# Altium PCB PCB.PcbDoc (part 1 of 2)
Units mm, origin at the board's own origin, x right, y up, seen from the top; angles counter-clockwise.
Board outline 41 x 25.36 mm, 4 copper layers (TOP, GND, SIG, BOTTOM), stack 1.586 mm thick; 138 components, 30 nets, 293 pads, 110 vias.
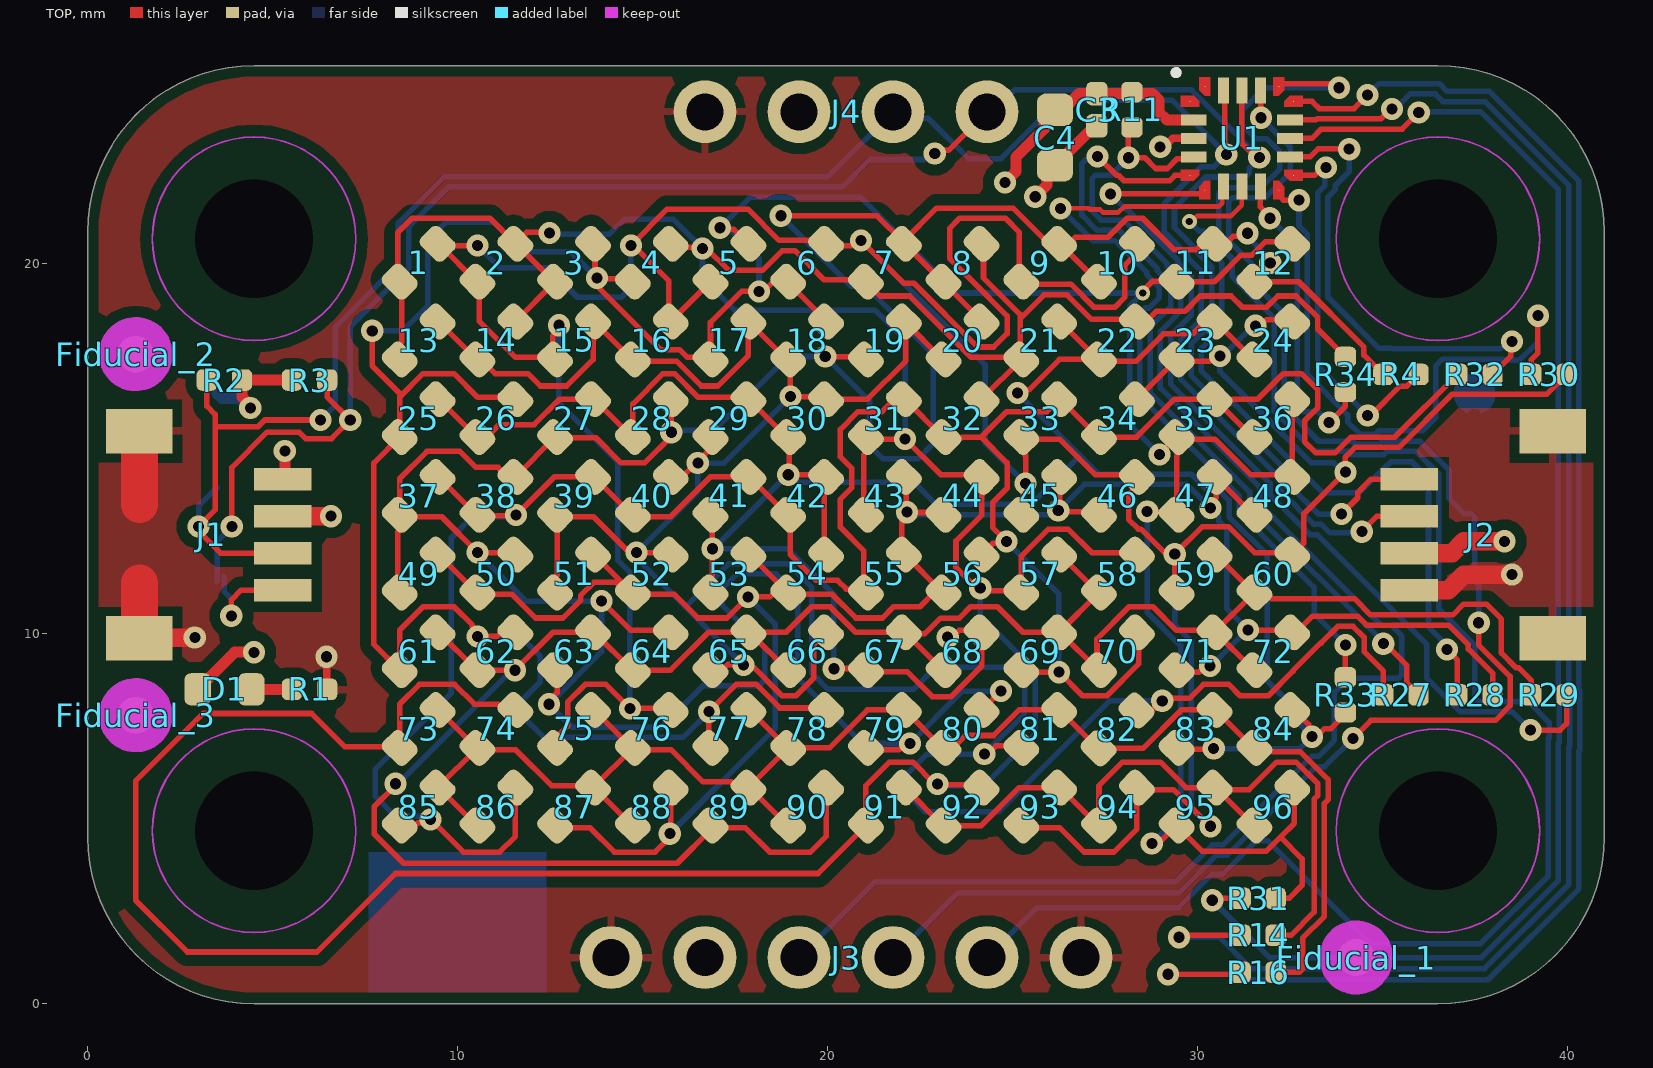
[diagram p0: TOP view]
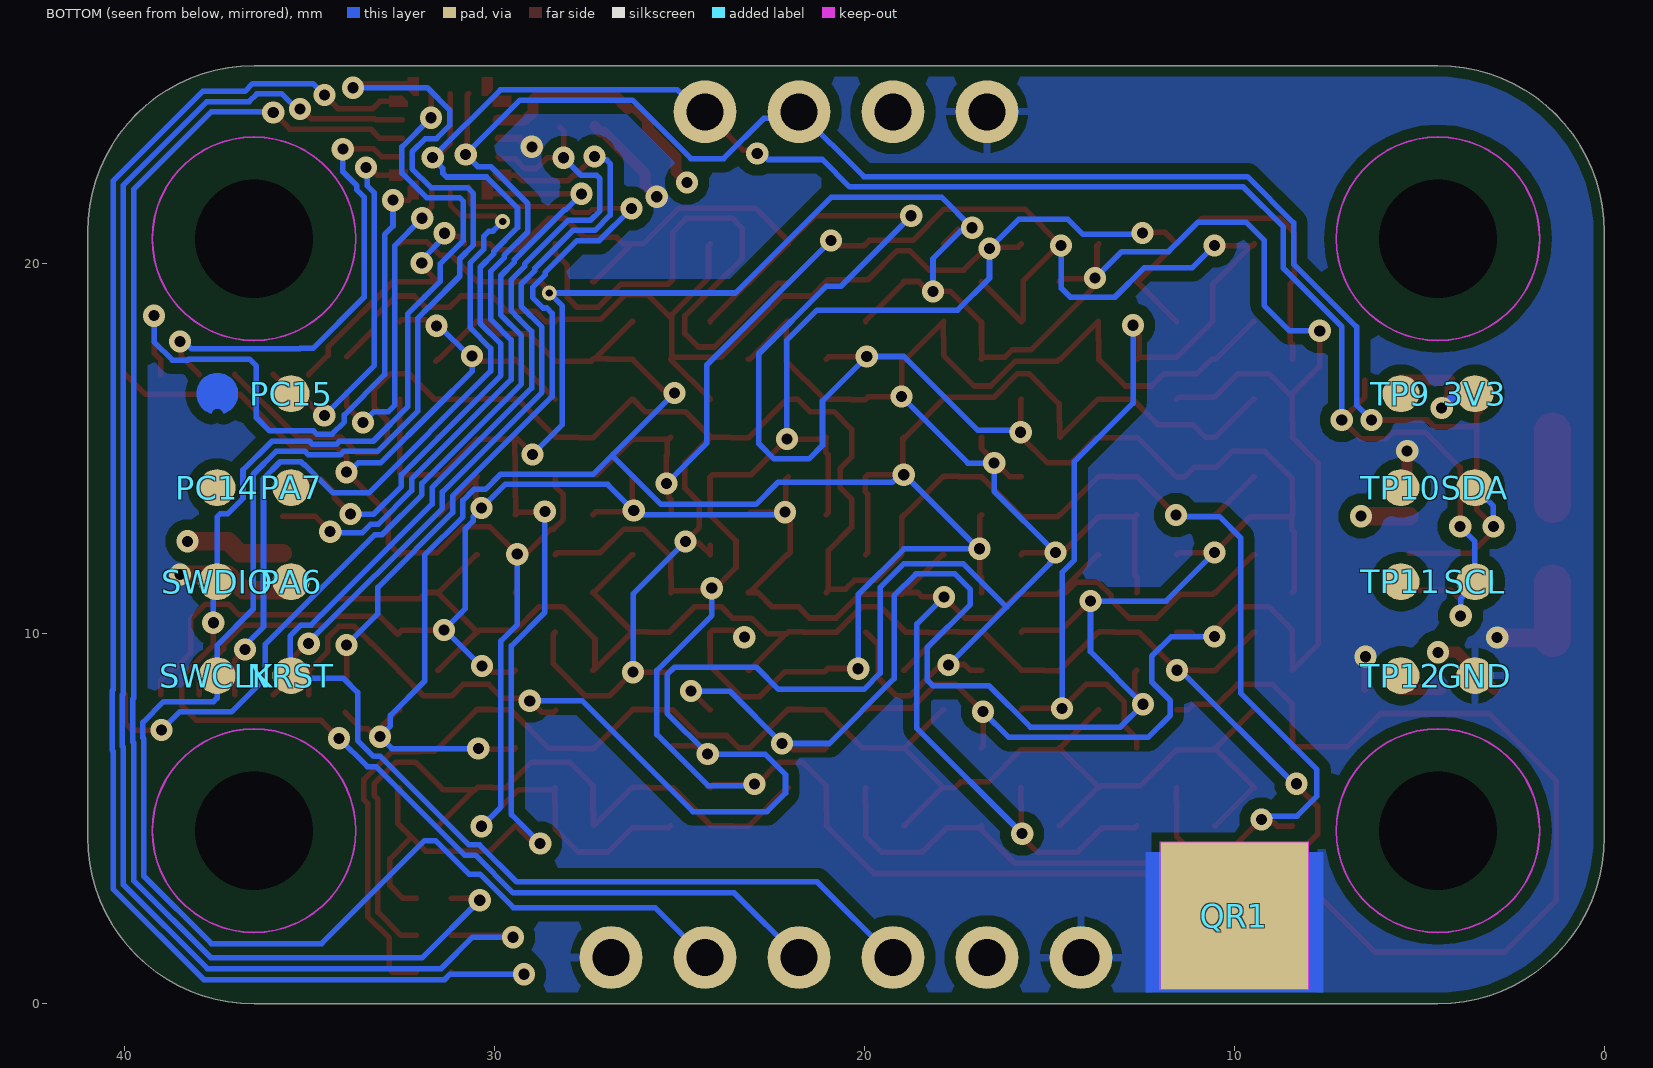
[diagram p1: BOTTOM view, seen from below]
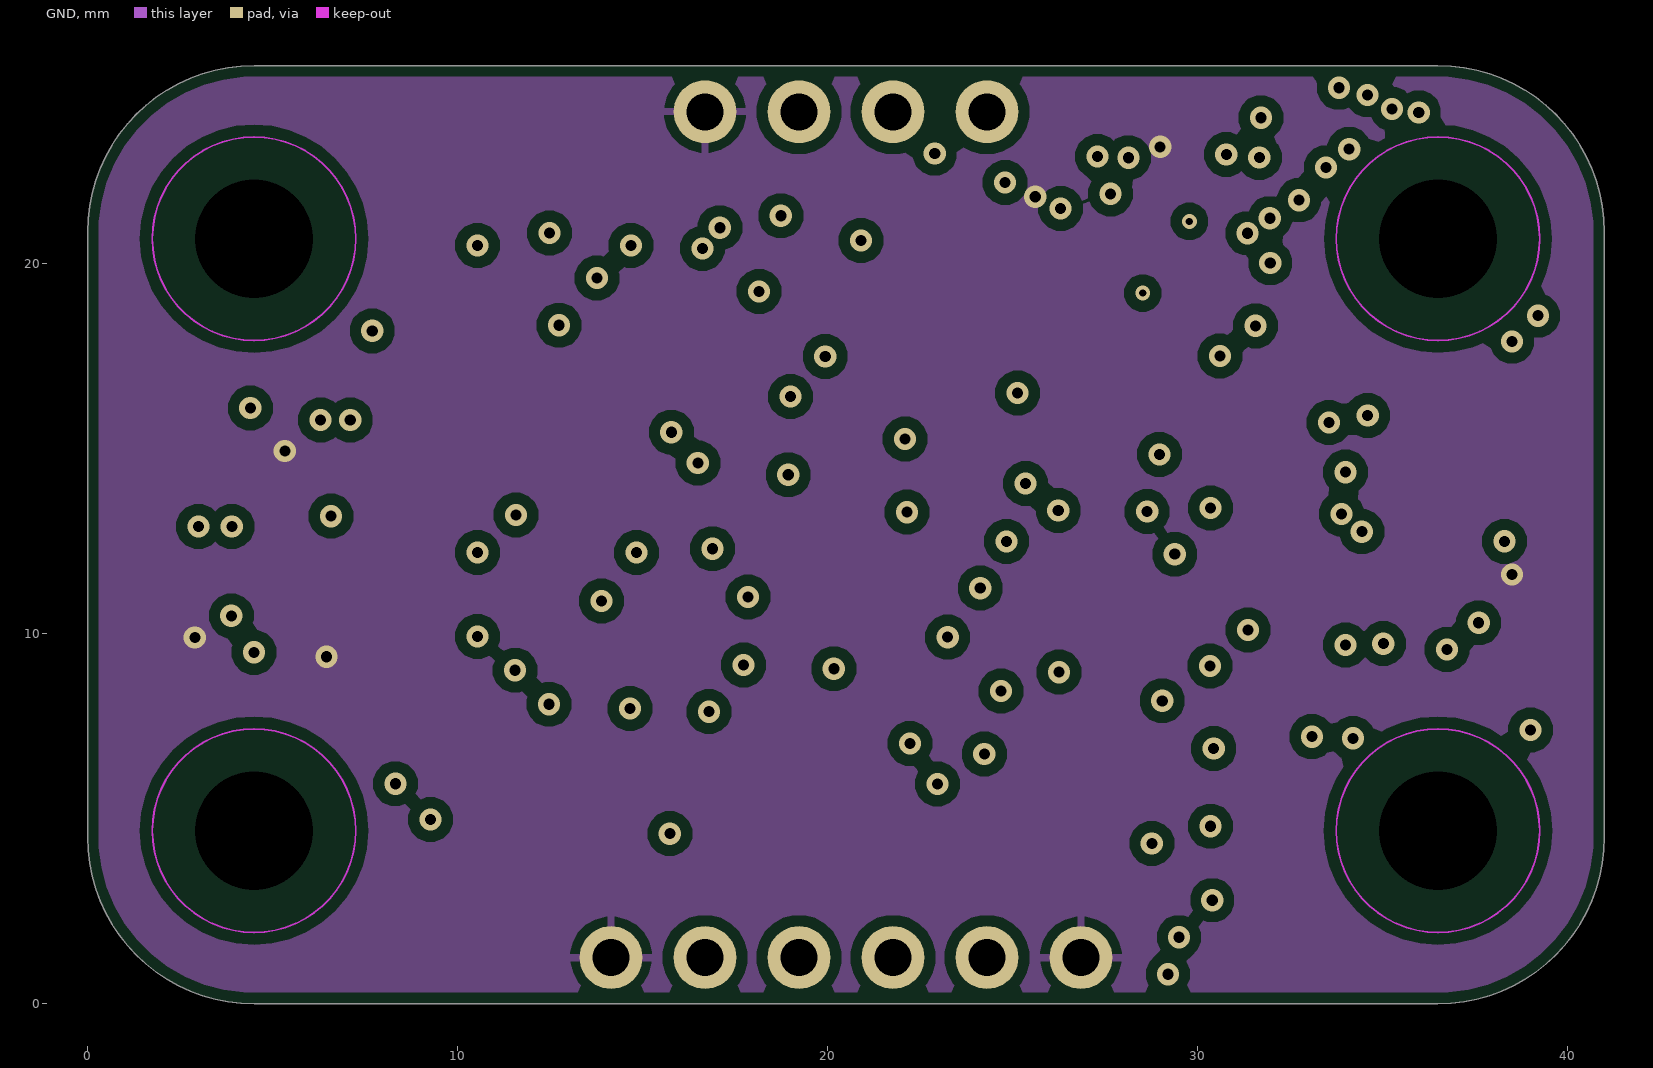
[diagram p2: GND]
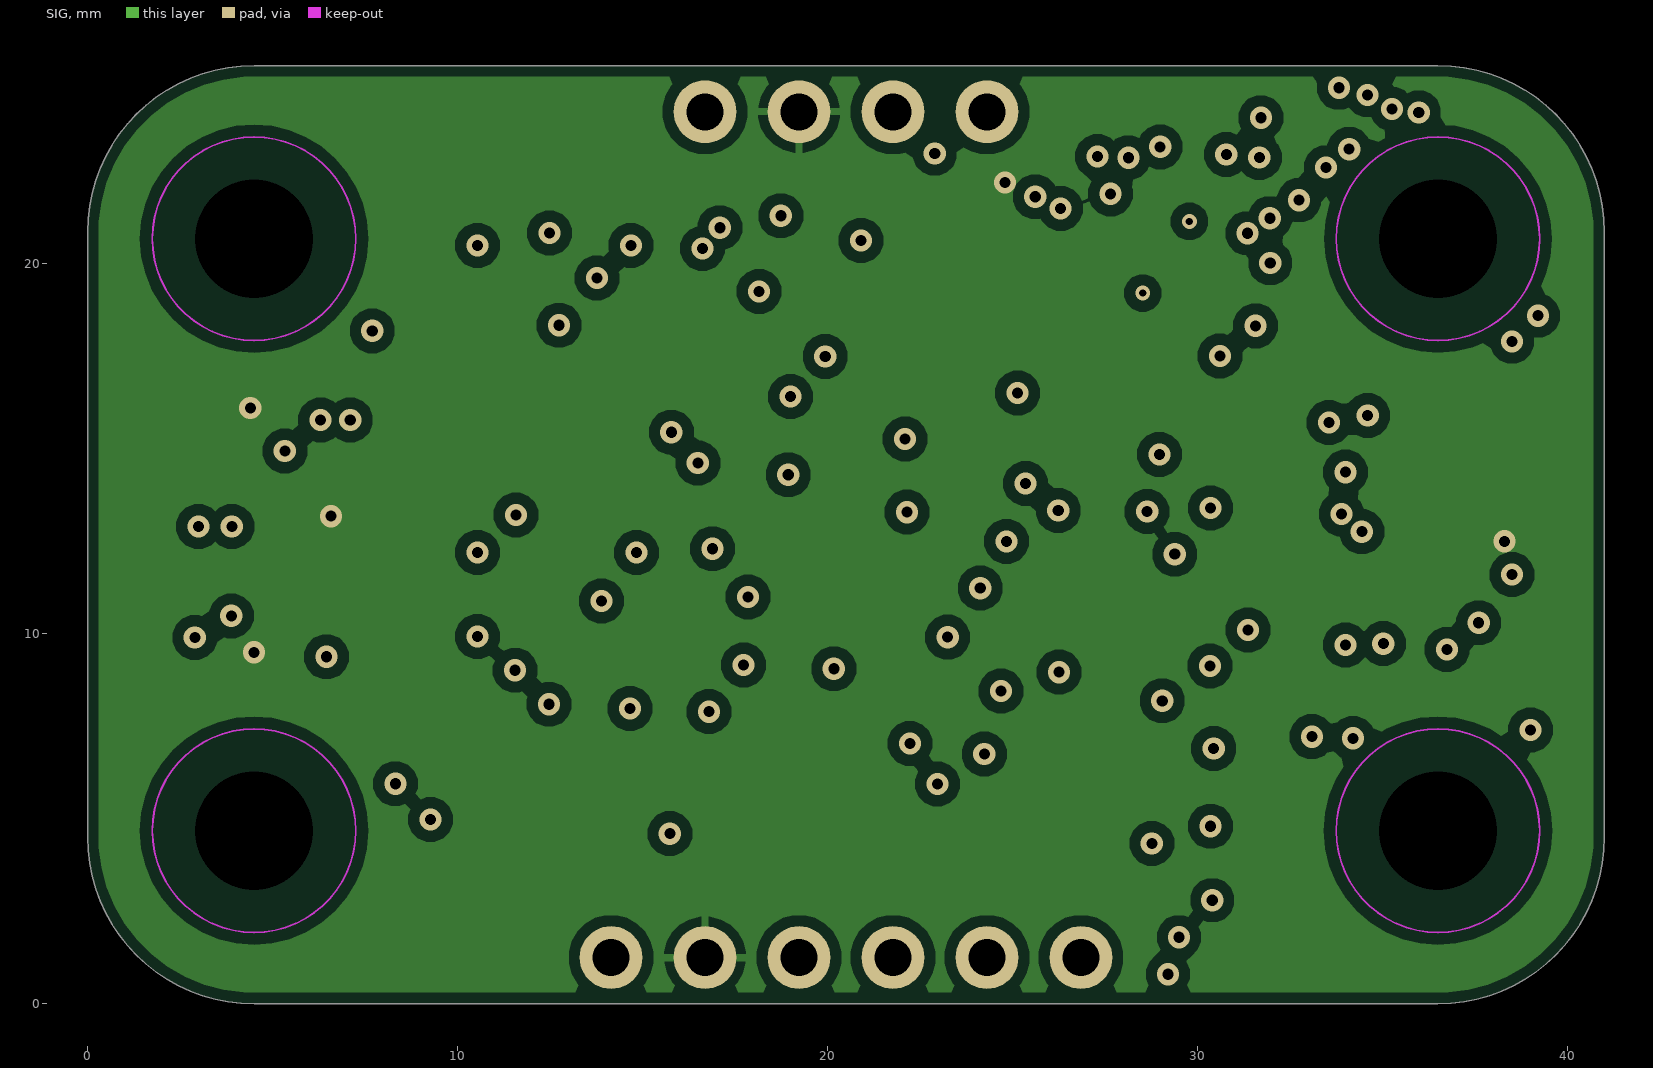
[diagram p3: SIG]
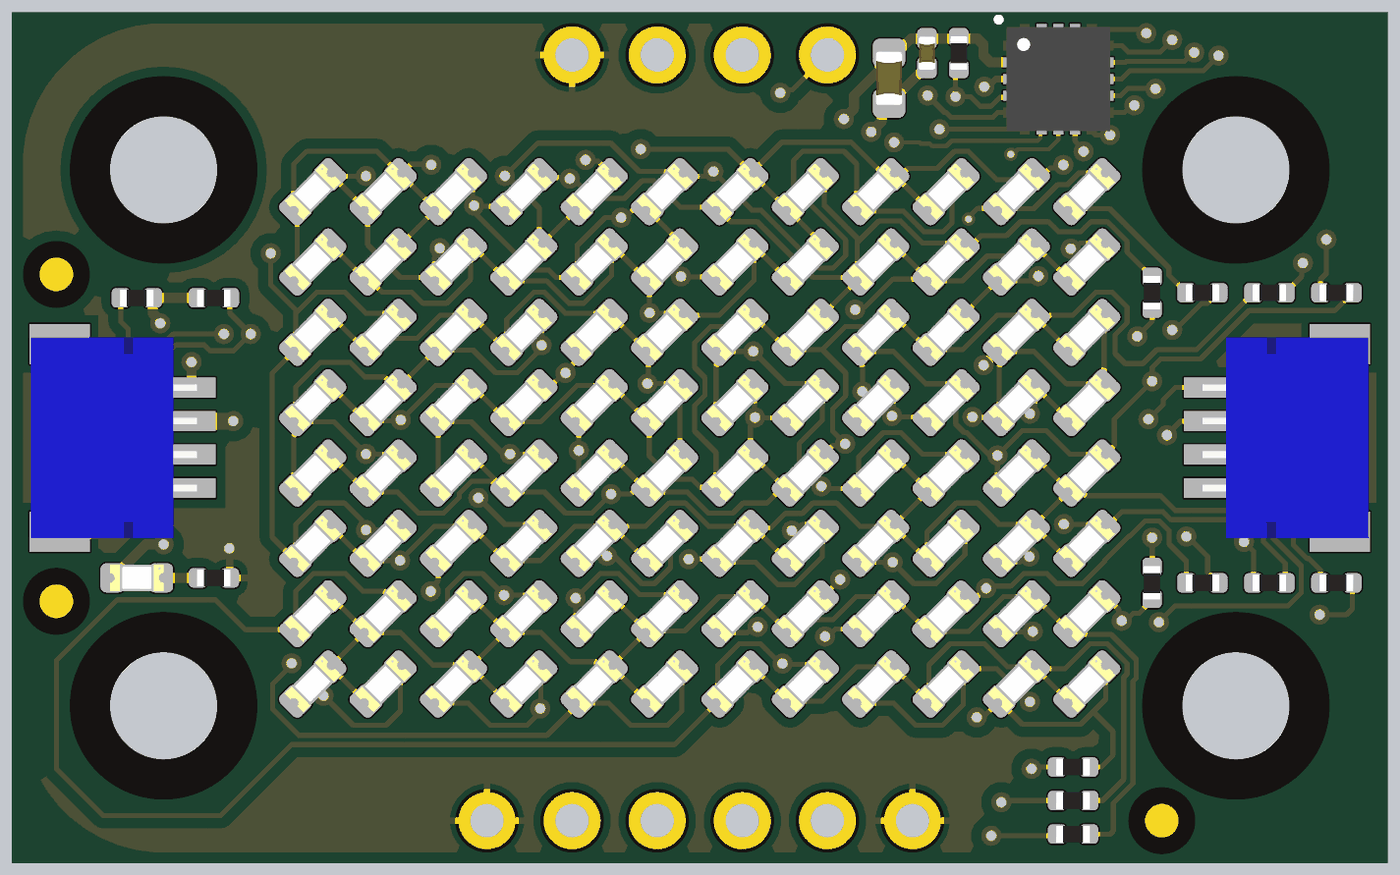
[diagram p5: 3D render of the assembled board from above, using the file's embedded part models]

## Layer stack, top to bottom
Top Solder: solder mask 0.01, Solder Resist, Dk 3.5
TOP: signal copper 0.018
Dielectric 1: prepreg 0.14, PP-014, Dk 4.2
GND: signal copper 0.035
Dielectric2: core 1.2, FR-4, Dk 4.8
SIG: signal copper 0.035
Dielectric3: prepreg 0.14, PP-014, Dk 4.2
BOTTOM: signal copper 0.018
Bottom Solder: solder mask 0.01, Solder Resist, Dk 3.5

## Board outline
0,4.5 ccw(c4.5,4.5) 4.5,0 36.5,0 ccw(c36.5,4.5) 41,4.5 41,20.86 ccw(c36.5,20.86) 36.5,25.36 4.5,25.36 ccw(c4.5,20.86) 0,20.86

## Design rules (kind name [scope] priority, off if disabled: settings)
BoardOutlineClearance Mousebites [(ObjectKind = 'Pad') And (Name = 'Free-MOUSEBITE')] p1: gap=0 ignorepadtopadclearanceinfootprint=FALSE
BoardOutlineClearance Silks [(OnLayer('Top Overlay') OR OnLayer('Bottom Overlay'))] p2: gap=0 ignorepadtopadclearanceinfootprint=FALSE
BoardOutlineClearance [All] p3: gap=0.3 ignorepadtopadclearanceinfootprint=FALSE
Clearance COPPER_0.3mm [All] p1: gap=0.127 ignorepadtopadclearanceinfootprint=FALSE except(0.3: Arc-Fill Arc-Poly Arc-Region Track-Fill Track-Poly Track-Region SMDPad-Fill SMDPad-Poly SMDPad-Region THPad-Fill THPad-Poly THPad-Region Via-Fill Via-Poly Via-Region Fill-Fill Fill-Poly Fill-Region Poly-Poly Poly-Region Region-Region)
Clearance "Generic clearance 0.15mm" [All] p2: gap=0.127 ignorepadtopadclearanceinfootprint=FALSE
ComponentClearance [All] p1: gap=0.2 collisioncheckmode=3 verticalgap=0 showdistances=TRUE
DiffPairsRouting USB [InDifferentialPairClass('USB')] p1: maxlimit=0.15 minlimit=0.15 mostfreqgap=0.15 toplayer_minwidth=0.15 toplayer_maxwidth=0.21 toplayer_prefwidth=0.2 midlayer1_minwidth=0.381 midlayer1_maxwidth=0.381 midlayer1_prefwidth=0.381 midlayer2_minwidth=0.381 midlayer2_maxwidth=0.381 midlayer2_prefwidth=0.381 bottomlayer_minwidth=0.15 bottomlayer_maxwidth=0.21 bottomlayer_prefwidth=0.2 impedanceprofiledriven=TRUE maxuncoupledlength=12.7
Height [All] p1: minheight=0 maxheight=30 prefheight=12.7
HoleSize [All] p1: absolutevalues=TRUE maxlimit=30 minlimit=0.2 maxpercent=80.000 minpercent=20.000
HoleToHoleClearance [All] p1: gap=0.25 allowstackedmicrovias=FALSE
MinimumAnnularRing [All] p1: minimumring=0.1
PlaneConnect [All] p1: pad.planeconnectstyle=Relief pad.reliefexpansion=0.508 pad.reliefentries=4 pad.reliefconductorwidth=0.254 pad.reliefairgap=0.254 via.planeconnectstyle=Direct via.reliefexpansion=0.508 via.reliefentries=4 via.reliefconductorwidth=0.254 via.reliefairgap=0.254
PolygonConnect [All] p1: thpad.connectstyle=Relief thpad.reliefconductorwidth=0.2 thpad.reliefentries=4 thpad.polygonreliefangle="90 Angle" thpad.airgapwidth=0.254 smdpad.connectstyle=Relief smdpad.reliefconductorwidth=0.2 smdpad.reliefentries=4 smdpad.polygonreliefangle="90 Angle" smdpad.airgapwidth=0.254 via.connectstyle=Direct via.reliefconductorwidth=0.254 via.reliefentries=4 via.polygonreliefangle="90 Angle" via.airgapwidth=0.254
RoomDefinition TOP [InComponentClass('TOP')] p1: confinementstyle=ConfineIn formatcopy=TRUE lockcomponents=FALSE outline 42.1,5.4 49.2,5.4 49.2,22.3 42.1,22.3
RoutingVias StandardVias [All] p1: holewidth=0.3 width=0.6 viastyle="Through Hole" minholewidth=0.2 minwidth=0.4 maxholewidth=0.3 maxwidth=0.6
SMDToCorner [All] p1: distance=39370
SilkToSilkClearance [All] p1: silktosilkclearance=0.2
SilkToSolderMaskClearance [IsPad] p1: minsilkscreentomaskgap=0.15 clearancetoexposedcopper=TRUE
SolderMaskExpansion VIAtented [IsVia] p1: expansion=0.102 istentingtop=TRUE
SolderMaskExpansion [All] p2: expansion=0.05 istentingtop=FALSE
SupplyNets "Schematic Supply Nets_1" [InNet('+3V3')] p1: voltage=0.000
SupplyNets "Schematic Supply Nets" [InNet('GND')] p2: voltage=0.000
UnConnectedPin [All] p1:
UnRoutedNet [NOT WithinRoom('K36')] p1: checkbadconnections=TRUE
ViasUnderSMD [All] p1: allowed=FALSE
Width StandardTraces [All] p1: maxlimit=5 minlimit=0.127 preferedwidth=0.15 bottomlayer_minwidth=0.15 minimp=50.000000 maximp=50.000000 favimp=50.000000
21 further rules are at their usual default settings.

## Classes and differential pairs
component class U_LEDMATRIX: 1 2 3 4 5 6 7 8 9 10 11 12 13 14 15 16 17 18 19 20 21 22 23 24 25 26 27 28 29 30 31 32 33 34 35 36 37 38 39 40 41 42 43 44 45 46 47 48 49 50 51 52 53 54 55 56 57 58 59 60 61 62 63 64 65 66 67 68 69 70 71 72 73 74 75 76 77 78 79 80 81 82 83 84 85 86 87 88 89 90 91 92 93 94 95 96 R4 R14 R16 R27 R28 R29 R30 R31 R32 R33 R34
component class U_MICROCONTROLLER: C3 C4 R2 R3 R11 U1
component class TOP: 3V3 D1 Fiducial_1 Fiducial_2 Fiducial_3 GND J1 J2 J3 J4 NRST PA6 PA7 PC14 PC15 QR1 R1 SCL SDA SWCLK SWDIO TP9 TP10 TP11 TP12

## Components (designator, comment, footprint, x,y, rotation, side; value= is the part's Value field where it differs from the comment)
1 "LTST-C191TBKT-5A" LEDC1608X80N-AK 8.951,20.03 r225 top
2 "LTST-C191TBKT-5A" LEDC1608X80N-AK 11.051,20.03 r225 top
3 "LTST-C191TBKT-5A" LEDC1608X80N-AK 13.151,20.03 r225 top
3V3 "Test point 1.00mm" TP-1.00MM 3.5,16.49 r90 bottom
4 "LTST-C191TBKT-5A" LEDC1608X80N-AK 15.251,20.03 r225 top
5 "LTST-C191TBKT-5A" LEDC1608X80N-AK 17.351,20.03 r225 top
6 "LTST-C191TBKT-5A" LEDC1608X80N-AK 19.451,20.03 r225 top
7 "LTST-C191TBKT-5A" LEDC1608X80N-AK 21.551,20.03 r225 top
8 "LTST-C191TBKT-5A" LEDC1608X80N-AK 23.651,20.03 r225 top
9 "LTST-C191TBKT-5A" LEDC1608X80N-AK 25.751,20.03 r225 top
10 "LTST-C191TBKT-5A" LEDC1608X80N-AK 27.851,20.03 r225 top
11 "LTST-C191TBKT-5A" LEDC1608X80N-AK 29.951,20.03 r225 top
12 "LTST-C191TBKT-5A" LEDC1608X80N-AK 32.051,20.03 r225 top
13 "LTST-C191TBKT-5A" LEDC1608X80N-AK 8.951,17.93 r225 top
14 "LTST-C191TBKT-5A" LEDC1608X80N-AK 11.051,17.93 r225 top
15 "LTST-C191TBKT-5A" LEDC1608X80N-AK 13.151,17.93 r225 top
16 "LTST-C191TBKT-5A" LEDC1608X80N-AK 15.251,17.93 r225 top
17 "LTST-C191TBKT-5A" LEDC1608X80N-AK 17.351,17.93 r225 top
18 "LTST-C191TBKT-5A" LEDC1608X80N-AK 19.451,17.93 r225 top
19 "LTST-C191TBKT-5A" LEDC1608X80N-AK 21.551,17.93 r225 top
20 "LTST-C191TBKT-5A" LEDC1608X80N-AK 23.65,17.93 r225 top
21 "LTST-C191TBKT-5A" LEDC1608X80N-AK 25.75,17.93 r225 top
22 "LTST-C191TBKT-5A" LEDC1608X80N-AK 27.85,17.93 r225 top
23 "LTST-C191TBKT-5A" LEDC1608X80N-AK 29.951,17.93 r225 top
24 "LTST-C191TBKT-5A" LEDC1608X80N-AK 32.051,17.93 r225 top
25 "LTST-C191TBKT-5A" LEDC1608X80N-AK 8.951,15.83 r225 top
26 "LTST-C191TBKT-5A" LEDC1608X80N-AK 11.051,15.83 r225 top
27 "LTST-C191TBKT-5A" LEDC1608X80N-AK 13.151,15.83 r225 top
28 "LTST-C191TBKT-5A" LEDC1608X80N-AK 15.251,15.83 r225 top
29 "LTST-C191TBKT-5A" LEDC1608X80N-AK 17.351,15.83 r225 top
30 "LTST-C191TBKT-5A" LEDC1608X80N-AK 19.451,15.83 r225 top
31 "LTST-C191TBKT-5A" LEDC1608X80N-AK 21.551,15.83 r225 top
32 "LTST-C191TBKT-5A" LEDC1608X80N-AK 23.65,15.83 r225 top
33 "LTST-C191TBKT-5A" LEDC1608X80N-AK 25.75,15.83 r225 top
34 "LTST-C191TBKT-5A" LEDC1608X80N-AK 27.851,15.83 r225 top
35 "LTST-C191TBKT-5A" LEDC1608X80N-AK 29.951,15.83 r225 top
36 "LTST-C191TBKT-5A" LEDC1608X80N-AK 32.051,15.83 r225 top
37 "LTST-C191TBKT-5A" LEDC1608X80N-AK 8.951,13.73 r225 top
38 "LTST-C191TBKT-5A" LEDC1608X80N-AK 11.051,13.73 r225 top
39 "LTST-C191TBKT-5A" LEDC1608X80N-AK 13.151,13.73 r225 top
40 "LTST-C191TBKT-5A" LEDC1608X80N-AK 15.251,13.73 r225 top
41 "LTST-C191TBKT-5A" LEDC1608X80N-AK 17.351,13.73 r225 top
42 "LTST-C191TBKT-5A" LEDC1608X80N-AK 19.451,13.73 r225 top
43 "LTST-C191TBKT-5A" LEDC1608X80N-AK 21.551,13.73 r225 top
44 "LTST-C191TBKT-5A" LEDC1608X80N-AK 23.65,13.73 r225 top
45 "LTST-C191TBKT-5A" LEDC1608X80N-AK 25.751,13.73 r225 top
46 "LTST-C191TBKT-5A" LEDC1608X80N-AK 27.851,13.73 r225 top
47 "LTST-C191TBKT-5A" LEDC1608X80N-AK 29.951,13.73 r225 top
48 "LTST-C191TBKT-5A" LEDC1608X80N-AK 32.051,13.73 r225 top
49 "LTST-C191TBKT-5A" LEDC1608X80N-AK 8.951,11.63 r225 top
50 "LTST-C191TBKT-5A" LEDC1608X80N-AK 11.051,11.63 r225 top
51 "LTST-C191TBKT-5A" LEDC1608X80N-AK 13.151,11.63 r225 top
52 "LTST-C191TBKT-5A" LEDC1608X80N-AK 15.251,11.63 r225 top
53 "LTST-C191TBKT-5A" LEDC1608X80N-AK 17.351,11.63 r225 top
54 "LTST-C191TBKT-5A" LEDC1608X80N-AK 19.45,11.63 r225 top
55 "LTST-C191TBKT-5A" LEDC1608X80N-AK 21.55,11.63 r225 top
56 "LTST-C191TBKT-5A" LEDC1608X80N-AK 23.651,11.63 r225 top
57 "LTST-C191TBKT-5A" LEDC1608X80N-AK 25.751,11.63 r225 top
58 "LTST-C191TBKT-5A" LEDC1608X80N-AK 27.851,11.63 r225 top
59 "LTST-C191TBKT-5A" LEDC1608X80N-AK 29.951,11.63 r225 top
60 "LTST-C191TBKT-5A" LEDC1608X80N-AK 32.051,11.63 r225 top
61 "LTST-C191TBKT-5A" LEDC1608X80N-AK 8.95,9.529 r225 top
62 "LTST-C191TBKT-5A" LEDC1608X80N-AK 11.051,9.53 r225 top
63 "LTST-C191TBKT-5A" LEDC1608X80N-AK 13.151,9.53 r225 top
64 "LTST-C191TBKT-5A" LEDC1608X80N-AK 15.251,9.53 r225 top
65 "LTST-C191TBKT-5A" LEDC1608X80N-AK 17.351,9.53 r225 top
66 "LTST-C191TBKT-5A" LEDC1608X80N-AK 19.451,9.53 r225 top
67 "LTST-C191TBKT-5A" LEDC1608X80N-AK 21.551,9.53 r225 top
68 "LTST-C191TBKT-5A" LEDC1608X80N-AK 23.651,9.53 r225 top
69 "LTST-C191TBKT-5A" LEDC1608X80N-AK 25.751,9.53 r225 top
70 "LTST-C191TBKT-5A" LEDC1608X80N-AK 27.851,9.53 r225 top
71 "LTST-C191TBKT-5A" LEDC1608X80N-AK 29.951,9.53 r225 top
72 "LTST-C191TBKT-5A" LEDC1608X80N-AK 32.051,9.53 r225 top
73 "LTST-C191TBKT-5A" LEDC1608X80N-AK 8.951,7.43 r225 top
74 "LTST-C191TBKT-5A" LEDC1608X80N-AK 11.051,7.43 r225 top
75 "LTST-C191TBKT-5A" LEDC1608X80N-AK 13.151,7.43 r225 top
76 "LTST-C191TBKT-5A" LEDC1608X80N-AK 15.251,7.43 r225 top
77 "LTST-C191TBKT-5A" LEDC1608X80N-AK 17.351,7.43 r225 top
78 "LTST-C191TBKT-5A" LEDC1608X80N-AK 19.451,7.43 r225 top
79 "LTST-C191TBKT-5A" LEDC1608X80N-AK 21.551,7.43 r225 top
80 "LTST-C191TBKT-5A" LEDC1608X80N-AK 23.651,7.43 r225 top
81 "LTST-C191TBKT-5A" LEDC1608X80N-AK 25.751,7.43 r225 top
82 "LTST-C191TBKT-5A" LEDC1608X80N-AK 27.838,7.417 r225 top
83 "LTST-C191TBKT-5A" LEDC1608X80N-AK 29.951,7.43 r225 top
84 "LTST-C191TBKT-5A" LEDC1608X80N-AK 32.051,7.43 r225 top
85 "LTST-C191TBKT-5A" LEDC1608X80N-AK 8.951,5.33 r225 top
86 "LTST-C191TBKT-5A" LEDC1608X80N-AK 11.051,5.33 r225 top
87 "LTST-C191TBKT-5A" LEDC1608X80N-AK 13.151,5.33 r225 top
88 "LTST-C191TBKT-5A" LEDC1608X80N-AK 15.251,5.33 r225 top
89 "LTST-C191TBKT-5A" LEDC1608X80N-AK 17.351,5.33 r225 top
90 "LTST-C191TBKT-5A" LEDC1608X80N-AK 19.451,5.33 r225 top
91 "LTST-C191TBKT-5A" LEDC1608X80N-AK 21.551,5.33 r225 top
92 "LTST-C191TBKT-5A" LEDC1608X80N-AK 23.651,5.33 r225 top
93 "LTST-C191TBKT-5A" LEDC1608X80N-AK 25.751,5.33 r225 top
94 "LTST-C191TBKT-5A" LEDC1608X80N-AK 27.851,5.33 r225 top
95 "LTST-C191TBKT-5A" LEDC1608X80N-AK 29.951,5.33 r225 top
96 "LTST-C191TBKT-5A" LEDC1608X80N-AK 32.051,5.33 r225 top
C3 "0402B104K160CT" CAP-0402 27.28,24.165 r270 top value=100nF
C4 "GRM188R61C475KAAJD" CAP-0603 26.15,23.415 r90 top value=4.7µF
D1 "HSMG-C190" LEDC1608X80N-AK 3.7,8.5 r180 top
Fiducial_1 "Fiducial mark 1mm" "Fiducial mark 1mm-Footprint-1" 34.29,1.25 r270 top
Fiducial_2 "Fiducial mark 1mm" "Fiducial mark 1mm-Footprint-1" 1.3,17.56 r270 top
Fiducial_3 "Fiducial mark 1mm" "Fiducial mark 1mm-Footprint-1" 1.3,7.8 r270 top
GND "Test point 1.00mm" TP-1.00MM 3.5,8.87 r90 bottom
J1 "SM04B-SRSS-TB(LF)(SN)" SM04B-SRSS-TB(LF)(SN)-Footprint-1 3.337,12.68 r90 top locked
J2 "SM04B-SRSS-TB(LF)(SN)" SM04B-SRSS-TB(LF)(SN)-Footprint-1 37.663,12.68 r270 top locked
J3 "HEADER TH 2.54mm VERT. 1x006POS" "PIN HEADER 2.54mm VERT. 1x6POS" 20.5,1.25 r0 top
J4 "HEADER TH 2.54mm VERT. 1x004POS" "PIN HEADER 2.54mm VERT. 1x4POS-Footprint-1" 20.5,24.11 r0 top
NRST "Test point 1.00mm" TP-1.00MM 35.5,8.87 r180 bottom
PA6 "Test point 1.00mm" TP-1.00MM 35.5,11.41 r180 bottom
PA7 "Test point 1.00mm" TP-1.00MM 35.5,13.95 r180 bottom
PC14 "Test point 1.00mm" TP-1.00MM 37.5,13.95 r180 bottom
PC15 "Test point 1.00mm" TP-1.00MM 35.5,16.49 r180 bottom
QR1 "QR CODE 4x4mm" "QR CODE 4x4mm" 10,2.38 r180 bottom
R1 "CRCW04021K00FKEDC" RES-0402 6,8.5 r180 top value=1k
R2 "RC0402FR-074K7L" RES-0402 3.7,16.86 r0 top value=4.7k
R3 "RC0402FR-074K7L" RES-0402 6,16.86 r180 top value=4.7k
R4 "RC0402FR-0710RL" RES-0402 35.5,17.01 r0 top value=10
R11 "RC0402FR-074K7L" RES-0402 28.23,24.165 r270 top value=4.7k
R14 "RC0402FR-0710RL" RES-0402 31.64,1.85 r180 top value=10
R16 "RC0402FR-0710RL" RES-0402 31.64,0.85 r180 top value=10
R27 "RC0402FR-0710RL" RES-0402 35.5,8.35 r0 top value=10
R28 "RC0402FR-0710RL" RES-0402 37.5,8.35 r180 top value=10
R29 "RC0402FR-0710RL" RES-0402 39.5,8.35 r0 top value=10
R30 "RC0402FR-0710RL" RES-0402 39.5,17.01 r180 top value=10
R31 "RC0402FR-0710RL" RES-0402 31.64,2.85 r180 top value=10
R32 "RC0402FR-0710RL" RES-0402 37.5,17.01 r0 top value=10
R33 "RC0402FR-0710RL" RES-0402 34,8.35 r90 top value=10
R34 "RC0402FR-0710RL" RES-0402 34,17.01 r270 top value=10
SCL "Test point 1.00mm" TP-1.00MM 3.5,11.41 r90 bottom
SDA "Test point 1.00mm" TP-1.00MM 3.5,13.95 r90 bottom
SWCLK "Test point 1.00mm" TP-1.00MM 37.5,8.87 r180 bottom
SWDIO "Test point 1.00mm" TP-1.00MM 37.5,11.41 r180 bottom
TP9 "Test point 1.00mm" TP-1.00MM 5.5,16.49 r0 bottom
TP10 "Test point 1.00mm" TP-1.00MM 5.5,13.95 r0 bottom
TP11 "Test point 1.00mm" TP-1.00MM 5.5,11.41 r0 bottom
TP12 "Test point 1.00mm" TP-1.00MM 5.5,8.87 r0 bottom
U1 "STM32C011F6U6TR" UFQFPN20 31.2,23.39 r0 top

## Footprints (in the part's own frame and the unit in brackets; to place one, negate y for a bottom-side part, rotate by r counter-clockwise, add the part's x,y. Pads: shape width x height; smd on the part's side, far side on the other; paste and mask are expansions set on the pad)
CAP-0402 [mm] "Chip Capacitor, 2-Leads, Body  0402 (in) 1005 (mm), IPC Medium Density"
  rrect52% 0.63x0.58 smd mask+0.05: 1(-0.435,0) 2(0.435,0)
  body extent -0.5,-0.25 0.5,0.25, height 0.5
CAP-0603 [mm] "Chip Capacitor, Body 0603 imperial,1.6x0.8mm, IPC High Density"
  rrect51% 0.87x0.97 smd mask+0.05: 1(-0.75,0) 2(0.75,0)
  body extent -0.8,-0.4 0.8,0.4, height 0.8
"Fiducial mark 1mm-Footprint-1" [mm]
  round 1 smd paste-10 mask+0.5: 1(0,0)
  TOP keep-out circle w1: c0,0 r0.5
LEDC1608X80N-AK [mm]
  rrect50% 0.72x0.87 smd: A(0.725,0) C(-0.725,0)
  body extent -0.8,-0.4 0.8,0.4, height 0.79
"PIN HEADER 2.54mm VERT. 1x4POS-Footprint-1" [mm]
  round 1.7 hole 1 mask+0.1: 1(-3.81,0) 2(-1.27,0) 3(1.27,0) 4(3.81,0)
"PIN HEADER 2.54mm VERT. 1x6POS" [mm]
  round 1.7 hole 1 mask+0.1: 1(-6.35,0) 2(-3.81,0) 3(-1.27,0) 4(1.27,0) 5(3.81,0) 6(6.35,0)
"QR CODE 4x4mm" [mm]
  rect 4x4 smd paste-2539.97 mask+0.1: PAD(0,0)
  TOP keep-out region: -2,2 2,2 2,-2 -2,-2
RES-0402 [mm] "Chip Resistor, 2-Leads, Body  0402 (in) 1005 (mm), IPC Medium Density"
  rrect51% 0.55x0.58 smd mask+0.05: 1(-0.475,0) 2(0.475,0)
  body extent -0.5,-0.25 0.5,0.25, height 0.34
SM04B-SRSS-TB(LF)(SN)-Footprint-1 [mm]
  rect 0.6x1.55 smd mask+0.05: 1(1.5,-1.937) 2(0.5,-1.937) 3(-0.5,-1.937) 4(-1.5,-1.937)
  rect 1.2x1.8 smd mask+0.05: FIX(-2.8,1.938) FIX(2.8,1.938)
  body extent -3,-2.16 3,2.8, height 2.98
TP-1.00MM [mm]
  rrect100% 1x1 smd paste-2.54: X(0,0)
UFQFPN20 [mm] "QFN, 20-Leads, Body 3.00x3.00mm, Pitch 0.50mm, IPC Medium Density"
  round 0.025 smd mask+0.05: 1(-1.4,1) 5(-1.4,-1) 6(-1,-1.4) 10(1,-1.4) 11(1.4,-1) 15(1.4,1) 16(1,1.4) 20(-1,1.4)
  rect 0.7x0.3 smd mask+0.05: 2(-1.3,0.5) 3(-1.3,0) 4(-1.3,-0.5) 12(1.3,-0.5) 13(1.3,0) 14(1.3,0.5)
  rect 0.3x0.7 smd mask+0.05: 7(-0.5,-1.3) 8(0,-1.3) 9(0.5,-1.3) 17(0.5,1.3) 18(0,1.3) 19(-0.5,1.3)
  TOP region: 1.65,-0.85 1.65,-1.15 1.3,-1.15 1.15,-1 1.15,-0.85
  TOP region: -1.15,1.3 -1,1.15 -0.85,1.15 -0.85,1.65 -1.15,1.65
  TOP region: -1.15,1 -1.15,0.85 -1.65,0.85 -1.65,1.15 -1.3,1.15
  TOP region: 1,1.15 0.85,1.15 0.85,1.65 1.15,1.65 1.15,1.3
  TOP region: 1.65,1.15 1.65,0.85 1.15,0.85 1.15,1 1.3,1.15
  TOP region: 1.15,-1.65 0.85,-1.65 0.85,-1.15 1,-1.15 1.15,-1.3
  TOP region: -0.85,-1.65 -1.15,-1.65 -1.15,-1.3 -1,-1.15 -0.85,-1.15
  TOP region: -1.3,-1.15 -1.15,-1 -1.15,-0.85 -1.65,-0.85 -1.65,-1.15
  silkscreen extent -1.8,1.75 -1.75,1.8, body extent -1.55,-1.55 1.55,1.55, height 0.6

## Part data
1 2 3 4 5 6 7 8 9 10 11 12 13 14 15 16 17 18 19 20 21 22 23 24 25 26 27 28 29 30 31 32 33 34 35 36 37 38 39 40 41 42 43 44 45 46 47 48 49 50 51 52 53 54 55 56 57 58 59 60 61 62 63 64 65 66 67 68 69 70 71 72 73 74 75 76 77 78 79 80 81 82 83 84 85 86 87 88 89 90 91 92 93 94 95 96: library part L0040-A.2, "LED SMD 0603 BLUE 468nm, water clear, 11-45 mcd, 138 deg", Manufacturer=Liteon
3V3 GND NRST PA6 PA7 PC14 PC15 SCL SDA SWCLK SWDIO TP9 TP10 TP11 TP12: library part UT0013-A.6, Manufacturer="This is not a component"
C3: library part C0012-A.15, "CAP CHIP 0402 100nF 10% 16V X7R", Case Code (Imperial)=0402, Dielectric=X7R, Manufacturer=Walsin, Tolerance=10%, Voltage=16V
C4: library part C0054-A.16, "CAP CHIP 0603 4.7uF 10% 16V X5R", Case Code (Imperial)=0603, Dielectric=X5R, Manufacturer=Murata, Manufacturer 3="Samsung Electro-Mechanics", Part number 2=GRM188R61C475KE11D, Part number 3=CL10A475KO8NNNC, Tolerance=10%, Voltage=16V
D1: library part L0009-A.5, "LED SMD 0603 GREEN/568 15mcd 120^", Manufacturer=Broadcom
Fiducial_1 Fiducial_2 Fiducial_3: library part UT0023-A.7, "Fiducial mark 1mm clearance 2mm"
J1 J2: library part J0005-A.3, "CONN JST SH 1mm 4POS HORIZONTAL TIN QWIIC", LCSC Part #=C160404, Manufacturer=JST
J3: library part J0167-A.4
J4: library part J0162-A.6
QR1: library part QR-0001-A.5, "QR CODE 4x4mm on layer 34 (This is not a component)", Manufacturer="This is not a component"
R1: library part R0007-A.24, "RES CHIP 0402 1k 1% 1/16W", Case Code (Imperial)=0402, Manufacturer=Vishay, Power=62.5mW, Temperature Coefficient=100ppm, Tolerance=1%
R2 R3 R11: library part R0013-A.24, "RES CHIP 0402 4k7 1% 1/16W", Case Code (Imperial)=0402, Manufacturer=YAGEO, Power=62.5mW, Temperature Coefficient=200ppm, Tolerance=1%
R4 R14 R16 R27 R28 R29 R30 R31 R32 R33 R34: library part R0170-A.23, "RES CHIP 0402 10R 1% 1/16W", Case Code (Imperial)=0402, Manufacturer=YAGEO, Power=62.5mW, Temperature Coefficient=200ppm, Tolerance=1%
U1: library part U0390-A.1, "IC Cortex M0, 32b MCU, 32KB Flash, 6KB RAM, VDD 2-3.6V, -40°C to 85°C, QFN20 3x3mm", Manufacturer="ST Microelectronics"

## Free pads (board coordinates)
  round 3 hole 3.2 unplated paste-2539.97 mask+1.3: MH(4.5,4.68) MH(4.5,20.68) MH(36.5,4.68) MH(36.5,20.68)

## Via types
v1: diameter 0.6, hole 0.3, TOP to BOTTOM, tented both sides, 108 vias
v2: diameter 0.4, hole 0.2, TOP to BOTTOM, tented both sides, 2 vias

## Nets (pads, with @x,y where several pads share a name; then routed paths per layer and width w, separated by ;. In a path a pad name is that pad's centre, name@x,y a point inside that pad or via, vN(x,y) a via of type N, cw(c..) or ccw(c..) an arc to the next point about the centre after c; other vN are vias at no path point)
+3V3: 3V3.X C3.1 C4.2 D1.A J1.2 J2.2 J3.2 J4.2 R2.2 R3.2 R11.1 U1.2 | length 16
  TOP w0.3: D1.A@2.975,8.5 3.98,9.505 4.495,9.505 v1(4.5,9.5) ; v1(4.4,16.1) 4.4,16.181 4.175,16.406 R2.2@4.175,16.86 R3.2@5.525,16.86 ; v1(24.8,22.2) 25.1,22.5 25.1,22.893 ; 25.1,22.8 25.1,22.893 ; C4.2@26.15,24.165 26.139,24.165 25.859,23.885 25.859,23.653 25.1,22.893 ; C4.2@26.4,24.2 26.8,24.6 28.79,24.6 28.965,24.424 28.965,24.096 29.172,23.89 U1.2@29.9,23.89
  TOP w0.5: J1.2@5.275,13.18 v1(6.58,13.18) ; J2.2@35.726,12.18 36.88,12.18 37.2,12.5 v1(38.3,12.5)
  BOTTOM w0.3: 3V3.X@3.5,16.49 3.634,16.356 4.09,16.356 4.346,16.1 v1(4.4,16.1)
GND: C3.2 C4.1 GND.X J1.1 J1.FIX J2.1 J2.FIX J3.1 J3.6 J4.1 QR1.PAD R1.1 U1.3 | length 13.3
  TOP w0.2: v1(6.459,9.381) 6.467,9.373 6.467,8.508 R1.1@6.475,8.5 ; v1(28.992,23.163) 29.1,23.163 29.327,23.39 U1.3@29.9,23.39
  TOP w0.3: J1.1@5.275,14.18 5.332,14.238 v1(5.332,14.942) ; v1(25.617,21.815) 25.932,22.13 25.932,22.438 27.06,23.565 27.14,23.565 27.28,23.705 C3.2@27.28,23.73
  TOP w0.5: J1.FIX@1.399,9.88 1.419,9.9 v1(2.9,9.9) ; J2.1@35.726,11.18 36.78,11.18 37.2,11.6 v1(38.5,11.6)
  TOP w1: J1.FIX@1.399,9.88 1.399,11.379 ; 1.399,13.499 J1.FIX@1.399,15.48
NetD1_C: D1.C R1.2 | length 1.1
  TOP w0.3: D1.C@4.425,8.5 R1.2@5.525,8.5
NetR4_2: R4.2 U1.11 | length 10.2
  TOP w0.15: U1.11@32.6,22.39 33.158,22.39 33.376,22.608 v1(33.471,22.608) ; v1(34.6,15.9) 34.684,15.9 35.476,16.693 35.658,16.693 R4.2@35.975,17.01
  BOTTOM w0.15: v1(33.471,22.608) 33.444,22.581 33.444,22.115 33.246,21.916 33.246,17.254 v1(34.6,15.9)
NetR14_2: R14.2 U1.14 | length 41.3
  TOP w0.15: v1(29.5,1.8) 29.55,1.85 R14.2@31.165,1.85 ; U1.14@32.5,23.89 33.2,23.89 33.231,23.921 34.954,23.921 35.217,24.185 v1(35.256,24.185)
  BOTTOM w0.15: v1(29.5,1.8) 30.59,1.8 31.44,0.95 37.764,0.95 40.031,3.217 40.031,6.938 40.056,6.963 40.056,8.348 40.031,8.373 40.031,22.127 37.773,24.385 36.633,24.385 36.424,24.594 35.747,24.594 35.338,24.185 v1(35.256,24.185)
NetR16_2: R16.2 U1.15 | length 42.5
  TOP w0.15: v1(29.2,0.8) 31.115,0.8 R16.2@31.165,0.85 ; U1.15@32.6,24.39 33.1,24.39 33.292,24.198 34.235,24.198 v1(34.597,24.56)
  BOTTOM w0.15: v1(29.2,0.8) 31.198,0.8 31.348,0.65 37.855,0.65 40.308,3.103 40.308,6.823 40.333,6.848 40.333,8.462 40.308,8.487 40.308,22.242 37.888,24.662 36.747,24.662 36.538,24.871 34.908,24.871 v1(34.597,24.56)
NetR27_2: R27.2 U1.5 | length 22.3
  TOP w0.15: v1(27.3,22.9) 27.806,22.394 27.86,22.394 28.007,22.248 28.806,22.248 28.809,22.245 29.246,22.245 29.391,22.39 U1.5@29.8,22.39 ; v1(35.023,9.734) 35.069,9.734 35.658,9.145 35.658,8.667 R27.2@35.975,8.35
  BOTTOM w0.15: v1(27.3,22.9) 27.214,22.814 26.979,22.814 26.873,22.709 26.873,21.319 27.285,20.907 27.885,20.907 28.91,19.882 28.91,19.817 29.277,19.45 29.277,18.849 28.719,18.292 28.719,16.528 31.409,13.838 31.409,13.393 35.023,9.778 v1(35.023,9.734)
NetR28_2: R28.2 U1.8 | length 21
  TOP w0.127: v2(29.781,21.146) 29.813,21.115 29.992,21.294 30.908,21.294 31.2,21.587 U1.8@31.2,22
  TOP w0.15: v1(36.741,9.575) 37.025,9.291 R28.2@37.025,8.35
  BOTTOM w0.15: v2(29.781,21.146) 30.041,20.886 30.153,20.886 30.295,20.744 30.295,20.39 30.662,20.024 30.662,18.275 30.104,17.718 30.104,17.102 33.397,13.809 34.366,13.809 35.124,14.567 35.152,14.567 35.237,14.652 35.791,14.652 36.244,14.199 36.244,10.188 36.741,9.69 v1(36.741,9.575)
NetR29_2: R29.2 U1.6 | length 25
  TOP w0.15: v1(27.652,21.892) 27.66,21.9 30.2,21.9 ; v1(39,7.4) 39.8,7.4 39.975,7.575 R29.2@39.975,8.35
  BOTTOM w0.15: v1(27.652,21.892) 28.084,21.461 28.115,21.461 29.464,20.111 29.464,20.046 29.831,19.679 29.831,18.62 29.273,18.062 29.273,16.757 31.963,14.068 31.963,13.755 33.034,12.684 33.234,12.684 36.202,9.715 36.202,8.798 37.109,7.891 38.509,7.891 v1(39,7.4)
NetR30_2: R30.2 U1.10 | length 16.8
  TOP w0.15: U1.10@32.2,21.99 32.2,21.842 32.321,21.721 v1(32.744,21.721) ; R30.2@39.025,17.01 39.025,17.412 39.2,17.587 v1(39.2,18.6)
  BOTTOM w0.15: v1(32.744,21.721) 32.744,21.019 32.969,20.794 32.969,17.006 34.059,15.916 34.059,15.731 34.392,15.398 34.808,15.398 34.893,15.483 36.079,15.483 36.438,15.841 36.438,17.238 36.623,17.423 38.267,17.423 38.292,17.398 38.708,17.398 39.2,17.89 v1(39.2,18.6)
NetR31_2: R31.2 U1.13 | length 38.8
  TOP w0.15: v1@30.425,2.825 v1(30.4,2.8) 30.45,2.85 R31.2@31.165,2.85 ; U1.13@32.5,23.39 33.092,23.39 33.346,23.644 35.533,23.644 v1(35.981,24.092)
  BOTTOM w0.15: v1(30.4,2.8) 31.952,1.248 37.67,1.248 39.754,3.332 39.754,7.052 39.779,7.077 39.779,8.233 39.754,8.258 39.754,22.012 37.658,24.108 35.997,24.108 v1(35.981,24.092)
NetR32_2: R32.2 U1.12 | length 12.7
  TOP w0.15: U1.12@32.5,22.89 33.043,22.89 33.263,23.11 34.09,23.11 v1(34.1,23.1) ; R32.2@37.975,17.01 38.465,17.5 38.465,17.865 v1(38.5,17.9)
  BOTTOM w0.15: v1(34.1,23.1) 34.1,22.49 33.721,22.111 33.721,22 33.523,21.801 33.523,19.097 34.907,17.713 35.257,17.713 35.267,17.703 38.187,17.703 38.384,17.9 v1(38.5,17.9)
NetR33_2: R33.2 U1.7 | length 21.7
  TOP w0.127: v1(26.3,21.5) 27.055,21.5 27.087,21.468 27.367,21.468 27.444,21.39 27.86,21.39 28.018,21.548 29.808,21.548 29.81,21.549 30.576,21.549 30.667,21.64 30.667,22.057 U1.7@30.7,22.09
  TOP w0.15: R33.2@34,8.825 v1(34,9.7)
  BOTTOM w0.15: v1(26.3,21.5) 27.17,20.63 27.77,20.63 28.633,19.767 28.633,19.702 28.971,19.364 28.971,19.093 28.684,18.807 28.586,18.807 28.442,18.663 28.442,16.413 31.132,13.724 31.132,13.278 33.154,11.256 33.154,10.546 v1(34,9.7)
NetR34_2: R34.2 U1.9 | length 8.3
  TOP w0.15: U1.9@31.7,22 31.7,21.542 31.955,21.287 v1(31.955,21.232) ; v1(33.557,15.708) 34,16.151 R34.2@34,16.535
  BOTTOM w0.15: v1(31.955,21.232) 32.692,20.495 32.692,16.183 32.869,16.007 33.259,16.007 v1(33.557,15.708)
PA13_SWDIO_1: J3.5 SWCLK.X U1.16 | length 51.7
  TOP w0.15: U1.16@32.2,24.79 32.284,24.874 33.591,24.874 33.705,24.76 v1(33.827,24.76)
  BOTTOM w0.15: J3.5@24.31,1.25 25.66,2.6 29.49,2.6 30.395,3.505 30.685,3.505 31.59,4.41 31.89,4.41 34.675,1.625 37.655,1.625 39.477,3.447 39.477,7.167 39.502,7.192 39.502,7.608 38.942,8.168 37.592,8.168 37.5,8.26 SWCLK.X@37.5,8.87 37.5,9.69 36.521,10.669 36.521,14.314 35.906,14.929 35.122,14.929 35.037,14.844 34.163,14.844 34.078,14.929 33.163,14.929 32.073,16.018 32.073,18.533 31.779,18.827 31.777,18.827 30.939,19.665 30.939,20.138 30.572,20.505 30.572,21.478 30.572,21.896 30.734,22.059 31.623,22.059 31.715,22.059 32.225,22.569 32.225,23.03 31.869,23.386 31.568,23.386 31.212,23.742 31.212,24.158 31.814,24.76 v1(33.827,24.76)
PA14_SWCLK_BOOT0_1: J3.4 SWDIO.X U1.17 | length 42.5
  TOP w0.15: U1.17@31.7,24.6 31.707,24.593 31.707,23.957 v1(31.714,23.95) ; v1(34.202,7.175) 34.687,7.66 38.054,7.66 38.452,8.058 38.452,8.851 37.6,9.703 v1(37.6,10.3)
  BOTTOM w0.15: J3.4@21.77,1.25 23.52,3 29.498,3 30.519,4.021 30.809,4.021 33.2,6.412 33.438,6.412 v1(34.202,7.175) ; v1(31.714,23.95) 32.502,23.162 32.502,22.454 31.829,21.782 30.937,21.782 30.849,21.694 30.849,20.854 30.849,20.62 31.464,20.005 31.464,19.532 31.891,19.104 31.894,19.104 32.35,18.648 32.35,16.133 33.277,15.206 34.192,15.206 34.277,15.121 34.923,15.121 35.008,15.206 36.02,15.206 36.798,14.428 36.798,13.659 37.209,13.248 37.412,13.248 37.5,13.16 SWDIO.X@37.5,11.41 37.6,11.31 v1(37.6,10.3)
PF2_N\R\S\T\_1: J3.3 NRST.X R11.2 U1.4 | length 42.2
  TOP w0.15: R11.2@28.23,23.69 28.132,23.592 v1(28.132,22.867) 28.578,22.867 28.868,22.577 29.186,22.577 29.45,22.841 29.851,22.841 U1.4@29.9,22.89
  BOTTOM w0.15: J3.3@19.23,1.25 21.28,3.3 29.407,3.3 30.404,4.298 30.694,4.298 33.085,6.689 33.271,6.689 33.7,7.118 33.7,8.415 34.088,8.803 35.433,8.803 35.525,8.895 35.525,9.942 35.231,10.236 34.957,10.236 31.686,13.508 31.686,13.953 28.996,16.643 28.996,18.177 29.348,18.528 29.554,18.734 29.554,19.565 29.187,19.931 29.187,19.997 28,21.184 27.4,21.184 27.15,21.433 27.15,22.307 27.238,22.394 27.66,22.394 v1(28.132,22.867)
